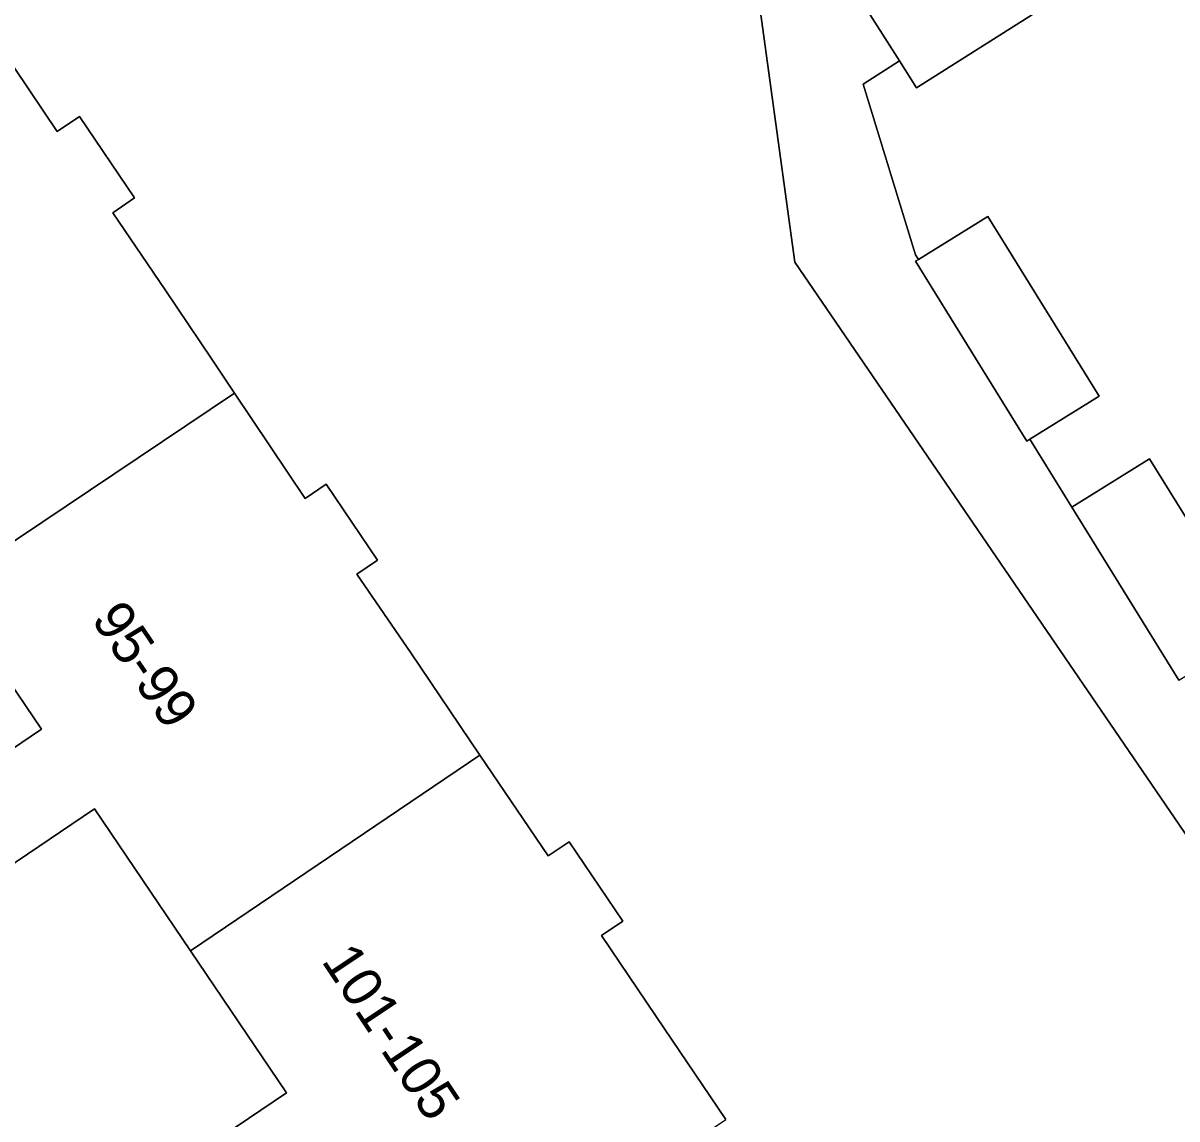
# Model space of a CAD drawing. Extents: x 159888 to 160761, y 384031 to 384750.
# Drawn here: x 160476.83 to 160505.78, y 384230.94 to 384258.44 of the extents above; entities that cross this region are included whole.
import ezdxf

# ---------------------------------------------------------------- set-up
doc = ezdxf.new("R2010")
doc.units = 0
for name, color, linetype in [('IMGEO_Erf', 7, 'Continuous'), ('IMGEO_Pand', 7, 'Continuous'), ('IMGEO_Pand_nummerreeks', 7, 'Continuous'), ('IMGEO_Voetpad_open', 7, 'Continuous')]:
    doc.layers.add(name, color=color, linetype=linetype)

msp = doc.modelspace()

# ---------------------------------------------------------------- linework, layer by layer
at = {"layer": 'IMGEO_Erf'}
for points in [[(160506.641, 384237.151), (160496.195, 384252.433), (160495.148, 384260.052)], [(160503.615, 384259.58), (160499.247, 384256.809), (160498.82, 384257.484), (160497.908, 384256.906), (160499.224, 384252.618), (160499.296, 384252.502), (160501.038, 384253.581), (160503.831, 384249.072), (160502.088, 384247.993), (160503.142, 384246.291), (160505.097, 384247.502), (160507.791, 384243.152)], [(160475.9, 384258.364), (160477.691, 384255.713), (160478.252, 384256.091), (160479.631, 384254.049), (160479.083, 384253.675), (160480.402, 384251.743), (160481.57, 384250), (160482.141, 384249.147), (160483.909, 384246.508), (160484.439, 384246.866), (160485.728, 384244.961), (160485.209, 384244.607), (160486.56, 384242.632), (160488.292, 384240.07), (160490.004, 384237.539), (160490.53, 384237.895), (160491.877, 384235.904), (160491.345, 384235.546), (160492.715, 384233.511), (160494.461, 384230.928)], [(160475.029, 384239.193), (160477.292, 384240.723), (160474.883, 384244.285)], [(160481.204, 384230.085), (160483.446, 384231.601), (160481.037, 384235.163), (160478.627, 384238.726), (160476.375, 384237.203)]]:
    msp.add_lwpolyline(points, dxfattribs=at)
at = {"layer": 'IMGEO_Pand'}
for points in [[(160503.615, 384259.58), (160503.188, 384260.252), (160502.317, 384261.625), (160497.831, 384259.045), (160498.82, 384257.484), (160499.247, 384256.809)], [(160475.9, 384258.364), (160468.65, 384253.467), (160470.996, 384250), (160471.114, 384249.825), (160468.873, 384248.309), (160470.217, 384246.323), (160472.473, 384247.848), (160474.883, 384244.285), (160482.141, 384249.147), (160481.57, 384250), (160480.402, 384251.743), (160479.083, 384253.675), (160479.631, 384254.049), (160478.252, 384256.091), (160477.691, 384255.713)], [(160499.296, 384252.502), (160499.225, 384252.458), (160502.017, 384247.949), (160502.088, 384247.993), (160503.831, 384249.072), (160501.038, 384253.581)], [(160482.141, 384249.147), (160474.883, 384244.285), (160477.292, 384240.723), (160475.029, 384239.193), (160476.375, 384237.203), (160478.627, 384238.726), (160481.037, 384235.163), (160488.292, 384240.07), (160486.56, 384242.632), (160485.209, 384244.607), (160485.728, 384244.961), (160484.439, 384246.866), (160483.909, 384246.508)], [(160505.831, 384241.948), (160507.791, 384243.152), (160505.097, 384247.502), (160503.142, 384246.291)], [(160488.292, 384240.07), (160481.037, 384235.163), (160483.446, 384231.601), (160481.204, 384230.085), (160482.595, 384228.028), (160484.818, 384229.531), (160487.196, 384226.015), (160494.461, 384230.928), (160492.715, 384233.511), (160491.345, 384235.546), (160491.877, 384235.904), (160490.53, 384237.895), (160490.004, 384237.539)]]:
    msp.add_lwpolyline(points, close=True, dxfattribs=at)
at = {"layer": 'IMGEO_Voetpad_open'}
for points in [[(160495.148, 384260.052), (160496.195, 384252.433), (160506.641, 384237.151)], [(160505.831, 384241.948), (160503.142, 384246.291), (160502.088, 384247.993), (160502.017, 384247.949), (160499.225, 384252.458), (160499.296, 384252.502), (160499.224, 384252.618), (160497.908, 384256.906), (160498.82, 384257.484), (160497.831, 384259.045)]]:
    msp.add_lwpolyline(points, dxfattribs=at)

# ---------------------------------------------------------------- texts
at = {"layer": 'IMGEO_Pand_nummerreeks'}
for s, rotation, p in [('95-99', 304.234, (160478.528, 384243.477)), ('101-105', 303.621, (160484.302, 384234.905))]:
    msp.add_text(s, height=1, rotation=rotation, dxfattribs=at).set_placement(p)

doc.saveas('drawing.dxf')
